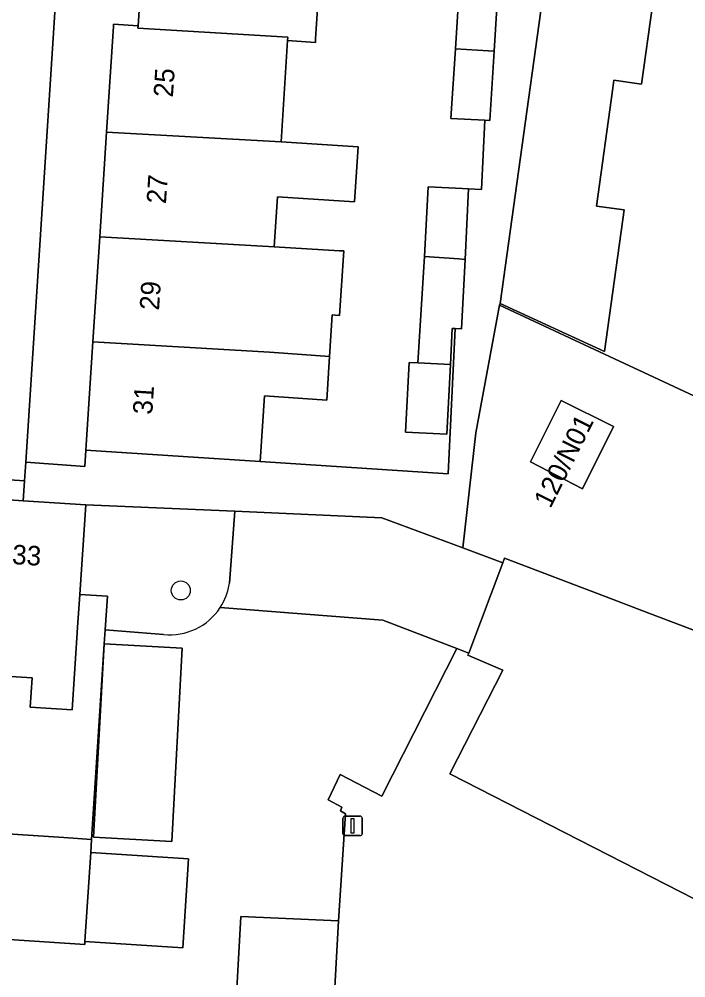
# Model space of a CAD drawing. Extents: x 160349 to 161355, y 381727 to 382854.
# Drawn here: x 160545.13 to 160579.38, y 382016.9 to 382066.09 of the extents above; entities that cross this region are included whole.
import ezdxf

# ---------------------------------------------------------------- set-up
doc = ezdxf.new("R2010")
doc.units = 0
for name, color, linetype in [('IMGEO_Boom', 7, 'Continuous'), ('IMGEO_Erf', 7, 'Continuous'), ('IMGEO_Groenvoorziening', 7, 'Continuous'), ('IMGEO_Inrit_onverhard', 7, 'Continuous'), ('IMGEO_Lichtmast', 7, 'Continuous'), ('IMGEO_Pand', 7, 'Continuous'), ('IMGEO_Pand_nummerreeks', 7, 'Continuous'), ('IMGEO_Parkeervlak_open', 7, 'Continuous'), ('IMGEO_Rijbaan_lokaal_open', 7, 'Continuous'), ('IMGEO_Voetpad_open', 7, 'Continuous')]:
    doc.layers.add(name, color=color, linetype=linetype)

msp = doc.modelspace()

# ---------------------------------------------------------------- linework, layer by layer
at = {"layer": 'IMGEO_Boom'}
msp.add_circle((160553.435, 382036.776), 0.489, dxfattribs=at)
at = {"layer": 'IMGEO_Erf'}
for points in [[(160552.29, 382081.786), (160552.642, 382087.17), (160552.972, 382092.23), (160552.992, 382092.532), (160551.734, 382092.608), (160552.089, 382098.046), (160552.44, 382103.429), (160552.792, 382108.822), (160553.148, 382114.275), (160550.061, 382114.509), (160545.472, 382043.358), (160548.507, 382043.145), (160548.561, 382043.975), (160548.924, 382049.541), (160549.276, 382054.926), (160549.626, 382060.294), (160549.98, 382065.716), (160549.987, 382065.83), (160551.243, 382065.748), (160551.586, 382070.997), (160551.938, 382076.393)], [(160585.328, 382072.575), (160578.792, 382074.891), (160577.106, 382062.766), (160575.681, 382062.964), (160575.624, 382062.548), (160574.783, 382056.502), (160576.207, 382056.304), (160575.198, 382049.046), (160569.845, 382051.509), (160569.801, 382051.419), (160583.376, 382045.082), (160584.584, 382049.97), (160581.845, 382050.785), (160582.28, 382052.244), (160581.448, 382059.536)]]:
    msp.add_lwpolyline(points, close=True, dxfattribs=at)
for points in [[(160560.581, 382068.448), (160560.36, 382065.078), (160560.349, 382064.903), (160558.923, 382064.996), (160558.584, 382059.796), (160562.545, 382059.54), (160562.361, 382056.726), (160558.399, 382056.972), (160558.231, 382054.407), (160561.59, 382054.212), (160561.802, 382054.2), (160561.586, 382050.894), (160561.388, 382050.907), (160561.218, 382050.918), (160561.08, 382048.789), (160560.935, 382046.547), (160557.732, 382046.76), (160557.512, 382043.39), (160567.163, 382042.759), (160567.537, 382050.217), (160567.374, 382050.225), (160567.281, 382048.367), (160567.102, 382044.8), (160564.981, 382044.907), (160565.16, 382048.478), (160565.616, 382048.455), (160565.953, 382053.912), (160566.134, 382057.494), (160567.897, 382057.406), (160568.217, 382057.39), (160568.879, 382057.357), (160569.057, 382060.907), (160567.313, 382060.994), (160567.538, 382064.574), (160567.765, 382068.179)], [(160542.951, 382041.54), (160545.344, 382041.383), (160545.411, 382042.407), (160530.648, 382043.401)], [(160541.648, 382024.475), (160547.428, 382024.097), (160548.856, 382024.004), (160549.494, 382034.035), (160549.547, 382034.761), (160549.671, 382036.484), (160548.248, 382036.577), (160548.136, 382034.873), (160547.858, 382030.645), (160545.703, 382030.787), (160545.801, 382032.284), (160542.262, 382032.515)], [(160582.049, 382019.806), (160567.258, 382027.358), (160569.969, 382032.694), (160568.184, 382033.456), (160568.223, 382033.56), (160567.62, 382033.798), (160563.756, 382026.216), (160561.616, 382027.336), (160561.005, 382026.029), (160561.7, 382025.66), (160561.631, 382025.459), (160561.904, 382025.308), (160561.543, 382019.82), (160560.417, 381999.666), (160555.404, 381999.955), (160555.394, 381999.801), (160586.709, 381984.411), (160587.131, 381985.496), (160591.533, 381996.816)]]:
    msp.add_lwpolyline(points, dxfattribs=at)
at = {"layer": 'IMGEO_Groenvoorziening'}
for points in [[(160556.219, 382040.853), (160548.55, 382041.172), (160548.248, 382036.577), (160549.671, 382036.484), (160549.547, 382034.761), (160552.548, 382034.524)], [(160555.93, 382037.156), (160556.219, 382040.853)]]:
    msp.add_lwpolyline(points, dxfattribs=at)
for centre, radius, start, end in [((160552.874, 382037.583), 3.085, 326.8329, 352.045), ((160552.886, 382037.579), 3.074, 263.6906, 326.778)]:
    msp.add_arc(centre, radius, start, end, dxfattribs=at)
at = {"layer": 'IMGEO_Inrit_onverhard'}
for points in [[(160581.541, 382038.749), (160581.885, 382039.937), (160583.376, 382045.082), (160569.801, 382051.419), (160568.593, 382044.873), (160567.919, 382038.965), (160569.977, 382038.199), (160570.064, 382038.428), (160575.278, 382036.453), (160577.484, 382035.617), (160595.189, 382028.91), (160596.411, 382032.134)], [(160574.062, 382042), (160571.403, 382043.381), (160572.974, 382046.52), (160575.653, 382045.185)]]:
    msp.add_lwpolyline(points, close=True, dxfattribs=at)
at = {"layer": 'IMGEO_Lichtmast'}
for p, q in [((160561.762, 382024.294), (160561.762, 382025.094)), ((160561.762, 382025.094), (160561.762, 382024.294)), ((160561.862, 382025.194), (160562.652, 382025.194)), ((160562.652, 382025.194), (160561.862, 382025.194)), ((160562.752, 382025.094), (160562.752, 382024.294)), ((160562.752, 382024.294), (160562.752, 382025.094)), ((160562.652, 382024.194), (160561.862, 382024.194)), ((160561.862, 382024.194), (160562.652, 382024.194))]:
    msp.add_line(p, q, dxfattribs=at)
msp.add_lwpolyline([(160562.182, 382025.069), (160562.332, 382025.069), (160562.332, 382024.319), (160562.182, 382024.319), (160562.182, 382025.069)], dxfattribs=at)
for centre, start, end in [((160561.862, 382025.094), 90, 180), ((160561.862, 382025.094), 90, 180), ((160562.652, 382025.094), 0, 90), ((160562.652, 382025.094), 360, 90), ((160561.862, 382024.294), 180, 270), ((160561.862, 382024.294), 180, 270), ((160562.652, 382024.294), 270, 0), ((160562.652, 382024.294), 270, 0)]:
    msp.add_arc(centre, 0.1, start, end, dxfattribs=at)
at = {"layer": 'IMGEO_Pand'}
for points in [[(160575.681, 382062.964), (160577.106, 382062.766), (160578.792, 382074.891), (160573.364, 382076.814), (160573.048, 382074.542), (160569.845, 382051.509), (160575.198, 382049.046), (160576.207, 382056.304), (160574.783, 382056.502), (160575.624, 382062.548)], [(160560.581, 382068.448), (160564.15, 382068.258), (160564.285, 382070.326), (160560.85, 382070.51), (160551.586, 382070.997), (160551.243, 382065.748), (160551.236, 382065.639), (160558.934, 382065.166), (160558.923, 382064.996), (160560.349, 382064.903), (160560.36, 382065.078)], [(160569.756, 382068.079), (160569.417, 382068.096), (160567.765, 382068.179), (160567.538, 382064.574), (160569.235, 382064.465), (160569.528, 382064.446)], [(160558.923, 382064.996), (160558.934, 382065.166), (160551.236, 382065.639), (160551.243, 382065.748), (160549.987, 382065.83), (160549.98, 382065.716), (160549.626, 382060.294), (160558.584, 382059.796)], [(160569.528, 382064.446), (160569.235, 382064.465), (160567.538, 382064.574), (160567.313, 382060.994), (160569.057, 382060.907), (160569.304, 382060.895)], [(160558.584, 382059.796), (160549.626, 382060.294), (160549.276, 382054.926), (160558.231, 382054.407), (160558.399, 382056.972), (160562.361, 382056.726), (160562.545, 382059.54)], [(160568.217, 382057.39), (160567.897, 382057.406), (160566.134, 382057.494), (160565.953, 382053.912), (160567.716, 382053.788), (160568.035, 382053.766)], [(160558.231, 382054.407), (160549.276, 382054.926), (160548.924, 382049.541), (160557.99, 382049), (160561.08, 382048.789), (160561.218, 382050.918), (160561.388, 382050.907), (160561.586, 382050.894), (160561.802, 382054.2), (160561.59, 382054.212)], [(160568.035, 382053.766), (160567.716, 382053.788), (160565.953, 382053.912), (160565.616, 382048.455), (160567.281, 382048.367), (160567.374, 382050.225), (160567.537, 382050.217), (160567.856, 382050.201)], [(160557.732, 382046.76), (160560.935, 382046.547), (160561.08, 382048.789), (160557.99, 382049), (160548.924, 382049.541), (160548.561, 382043.975), (160553.551, 382043.649), (160557.512, 382043.39)], [(160567.281, 382048.367), (160565.616, 382048.455), (160565.16, 382048.478), (160564.981, 382044.907), (160567.102, 382044.8)], [(160575.653, 382045.185), (160572.974, 382046.52), (160571.403, 382043.381), (160574.062, 382042)], [(160548.248, 382036.577), (160548.55, 382041.172), (160545.344, 382041.383), (160542.951, 382041.54), (160542.262, 382032.515), (160545.801, 382032.284), (160545.703, 382030.787), (160547.858, 382030.645), (160548.136, 382034.873)], [(160549.494, 382034.035), (160548.957, 382024.111), (160552.969, 382023.894), (160553.505, 382033.818)], [(160548.812, 382023.329), (160548.856, 382024.004), (160547.428, 382024.097), (160541.648, 382024.475), (160541.237, 382019.089), (160548.504, 382018.615), (160548.514, 382018.767)]]:
    msp.add_lwpolyline(points, close=True, dxfattribs=at)
msp.add_lwpolyline([(160595.189, 382028.91), (160577.484, 382035.617), (160575.278, 382036.453), (160570.064, 382038.428), (160569.977, 382038.199), (160568.223, 382033.56), (160568.184, 382033.456), (160569.969, 382032.694), (160567.258, 382027.358), (160582.049, 382019.806)], dxfattribs=at)
at = {"layer": 'IMGEO_Parkeervlak_open'}
for points in [[(160569.977, 382038.199), (160567.919, 382038.965), (160563.769, 382040.51), (160556.219, 382040.853), (160555.93, 382037.156)], [(160555.457, 382035.895), (160563.819, 382035.25), (160567.62, 382033.798), (160568.223, 382033.56), (160569.977, 382038.199)]]:
    msp.add_lwpolyline(points, dxfattribs=at)
for points in [[(160548.812, 382023.329), (160548.514, 382018.767), (160553.543, 382018.441), (160553.839, 382023.002)], [(160556.512, 382020.05), (160555.404, 381999.955), (160560.417, 381999.666), (160561.543, 382019.82)]]:
    msp.add_lwpolyline(points, close=True, dxfattribs=at)
msp.add_arc((160552.874, 382037.583), 3.085, 326.8329, 352.045, dxfattribs=at)
at = {"layer": 'IMGEO_Rijbaan_lokaal_open'}
for points in [[(160556.512, 382020.05), (160561.543, 382019.82), (160561.904, 382025.308), (160561.631, 382025.459), (160561.7, 382025.66), (160561.005, 382026.029), (160561.616, 382027.336), (160563.756, 382026.216), (160567.62, 382033.798), (160563.819, 382035.25), (160555.457, 382035.895)], [(160552.548, 382034.524), (160549.547, 382034.761), (160549.494, 382034.035), (160548.856, 382024.004), (160548.812, 382023.329), (160553.839, 382023.002), (160553.543, 382018.441), (160548.514, 382018.767), (160548.504, 382018.615), (160541.237, 382019.089), (160538.419, 382019.273), (160536.043, 382019.426), (160529.135, 382019.87), (160528.873, 382014.469)], [(160555.404, 381999.955), (160556.512, 382020.05)]]:
    msp.add_lwpolyline(points, dxfattribs=at)
msp.add_lwpolyline([(160549.494, 382034.035), (160553.505, 382033.818), (160552.969, 382023.894), (160548.957, 382024.111)], close=True, dxfattribs=at)
msp.add_arc((160552.886, 382037.579), 3.074, 263.6906, 326.778, dxfattribs=at)
at = {"layer": 'IMGEO_Voetpad_open'}
for points in [[(160541.81, 382045.609), (160532.964, 382046.126), (160528.807, 382045.931), (160528.662, 382043.535), (160530.648, 382043.401), (160545.411, 382042.407), (160545.472, 382043.358), (160550.061, 382114.509)], [(160569.756, 382068.079), (160569.528, 382064.446), (160569.304, 382060.895), (160569.057, 382060.907), (160568.879, 382057.357), (160568.217, 382057.39), (160568.035, 382053.766), (160567.856, 382050.201), (160567.537, 382050.217), (160567.163, 382042.759), (160557.512, 382043.39), (160553.551, 382043.649), (160548.561, 382043.975), (160548.507, 382043.145), (160545.472, 382043.358), (160545.411, 382042.407), (160545.344, 382041.383), (160548.55, 382041.172), (160556.219, 382040.853), (160563.769, 382040.51), (160567.919, 382038.965), (160568.593, 382044.873), (160569.801, 382051.419), (160569.845, 382051.509), (160573.048, 382074.542)]]:
    msp.add_lwpolyline(points, dxfattribs=at)

# ---------------------------------------------------------------- texts
at = {"layer": 'IMGEO_Pand_nummerreeks'}
for s, rotation, p in [('25', 86.2645, (160553.029, 382062.06)), ('27', 86.2668, (160552.672, 382056.597)), ('29', 86.2645, (160552.316, 382051.133)), ('31', 86.2645, (160551.966, 382045.782)), ('120/N01', 63.4551, (160572.418, 382040.946)), ('33', 356.2357, (160544.749, 382038.136))]:
    msp.add_text(s, height=1, rotation=rotation, dxfattribs=at).set_placement(p)

doc.saveas('drawing.dxf')
